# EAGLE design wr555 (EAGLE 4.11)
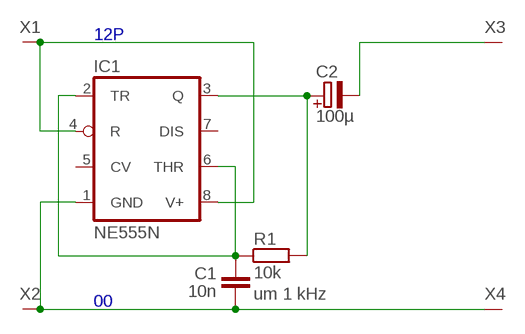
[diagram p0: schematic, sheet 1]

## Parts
C1  10n  C01  [C1]
C2  100µ  E01-8  [E01-8]
IC1  NE555N  [DIL08]
R1  10k  R01  [R01]
X1  PAD  [SMD-2MM]
X2  PAD  [SMD-2MM]
X3  PAD  [SMD-2MM]
X4  PAD  [SMD-2MM]

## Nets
00: C1.2 IC1.1(GND) X2.1 X4.1
12P: IC1.4(R) IC1.8(V+) X1.1
N$1: C2.- X3.1
N$4: C2.+ IC1.3(Q) R1.2
N$5: C1.1 IC1.2(TR) IC1.6(THR) R1.1
Unconnected: IC1.5(CV) IC1.7(DIS)

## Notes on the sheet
- um 1 kHz

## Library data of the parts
C1 = fu:C: Kondensator
C2 = fu:E: Elektrolytkondensator, gepolt
IC1 = linear:*555: TIMER
R1 = fu:R: Widerstand
X1-X4 = fu:PAD: Anschlussfeld

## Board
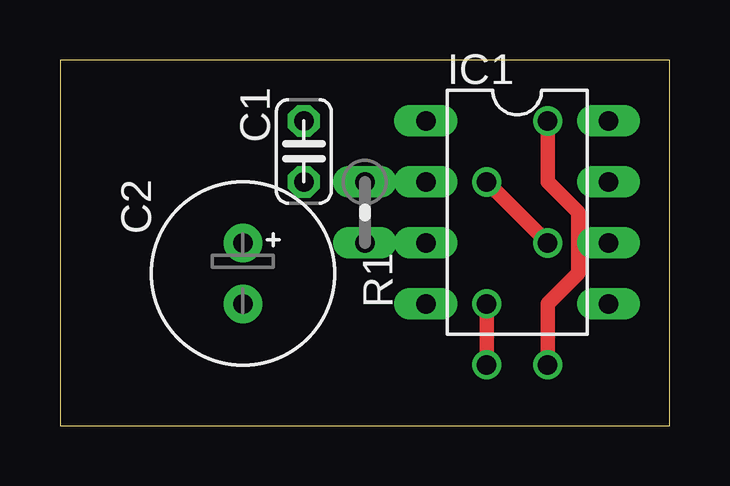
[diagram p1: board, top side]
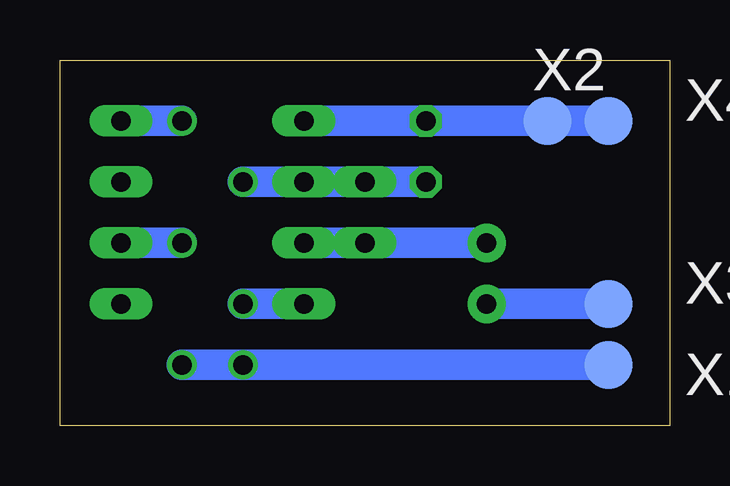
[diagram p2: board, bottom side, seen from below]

Size 25.4 x 15.24 mm. Coordinates in mm from the lower left corner, seen from the top.
Outline: 0,0 25.4,0 25.4,15.24 0,15.24 0,0
Copper layers (1+16): Top 0.035mm / dielectric 1.5mm / Bottom 0.035mm
Design rules "default": minimum track width 10mil, minimum drill 24mil, track to track 8mil, track to pad 8mil, pad to pad 8mil, via to via 8mil, smd to smd 8mil, copper to edge 40mil, drill to drill 8mil, minimum pad ring 10mil, minimum via ring 8mil, stop-mask expansion 4mil, vias tented up to drill 0mil, thermal gap 10mil
bRestrict: area 16.5,11.4 to 19.1,14; area 19.1,8.9 to 21.6,11.4; area 16.5,6.3 to 19.1,8.9; area 19.1,3.8 to 21.6,6.3; area 8.9,3.8 to 11.4,6.3

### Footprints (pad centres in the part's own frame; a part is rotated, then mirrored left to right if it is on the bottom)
C1 = drill 0.813 octagon: 1 -1.27,0; 2 1.27,0
E01-8 = drill 0.813 pad 1.6 round: + -1.27,0; - 1.27,0
DIL08 = drill 0.813 long: 1 -3.81,-3.81; 2 -1.27,-3.81; 3 1.27,-3.81; 4 3.81,-3.81; 5 3.81,3.81; 6 1.27,3.81; 7 -1.27,3.81; 8 -3.81,3.81
R01 = drill 0.813 long: 1 -1.27,0; 2 1.27,0
SMD-2MM = smd 2 x 2: 1 0,0

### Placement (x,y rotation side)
C1  10.16,11.43 90 top
C2  7.62,6.35 270 top
IC1  19.05,8.89 270 top
R1  12.7,8.89 270 top
X1  2.54,2.54 0 bottom
X2  5.08,12.7 0 bottom
X3  2.54,5.08 0 bottom
X4  2.54,12.7 0 bottom

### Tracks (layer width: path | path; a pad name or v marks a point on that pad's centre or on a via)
00
  Bottom 1.27: X4.1 X2.1 C1.2 IC1.1
12P  (via drill 0.81)
  Top 0.61: v17.78,2.54 v17.78,5.08 | v20.32,12.7 20.32,10.16 21.59,8.89 21.59,6.35 20.32,5.08 v20.32,2.54
  Bottom 1.27: X1.1 v17.78,2.54 v20.32,2.54 | v17.78,5.08 IC1.4 | v20.32,12.7 IC1.8
N$1
  Bottom 1.27: X3.1 C2.-
N$4
  Bottom 1.27: C2.+ R1.2 IC1.3
N$5  (via drill 0.81)
  Top 0.61: v17.78,10.16 v20.32,7.62
  Bottom 1.27: C1.1 R1.1 IC1.2 v17.78,10.16 | v20.32,7.62 IC1.6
